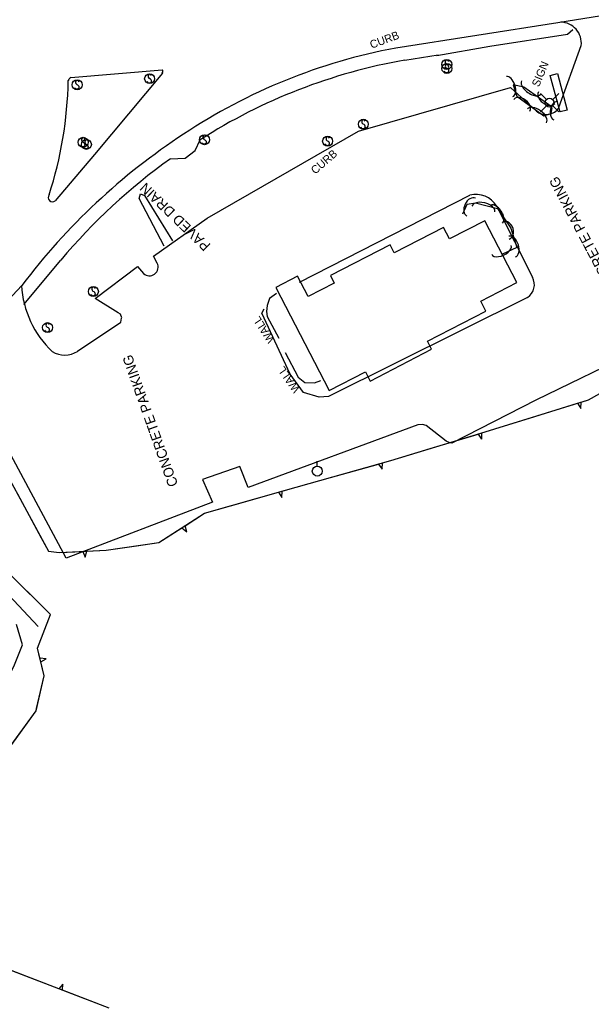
# Model space of a CAD drawing. Extents: x 978516 to 993312, y 1836504 to 1846212.
# Drawn here: x 980525.8 to 980811.4, y 1841850.4 to 1842344.4 of the extents above; entities that cross this region are included whole.
import ezdxf

# ---------------------------------------------------------------- set-up
doc = ezdxf.new("R2010")
doc.units = 0
for name, color, linetype in [('S_BUILDING', 7, 'Continuous'), ('S_CURB_ANNOT', 7, 'Continuous'), ('S_DROP_INLET', 7, 'Continuous'), ('S_EDGE_PAVEMENT', 7, 'Continuous'), ('S_PARKING', 7, 'Continuous'), ('S_PARKING_ANNOT', 7, 'Continuous'), ('S_SIDE_DRAIN', 7, 'Continuous'), ('S_SIDE_DRAIN_ANNOT', 7, 'Continuous'), ('S_SIDEWALK', 7, 'Continuous'), ('S_SIGN', 7, 'Continuous'), ('S_SIGN_ANNOT', 7, 'Continuous'), ('S_TREE', 7, 'Continuous'), ('S_UTILITY_POLE', 7, 'Continuous'), ('S_WALL', 7, 'Continuous'), ('S_WALL_ANNOT', 7, 'Continuous')]:
    doc.layers.add(name, color=color, linetype=linetype)

msp = doc.modelspace()

# ---------------------------------------------------------------- linework, layer by layer
at = {"layer": 'S_BUILDING'}
msp.add_lwpolyline([(980700.89, 1842163.85), (980731.67, 1842179.7), (980729.61, 1842183.71), (980758.77, 1842198.73), (980756.17, 1842203.79), (980774.22, 1842213.08), (980758.31, 1842243.96), (980740.63, 1842234.85), (980737.66, 1842240.61), (980712.96, 1842227.89), (980710.86, 1842231.94), (980681.03, 1842216.57), (980682.95, 1842212.83), (980669.89, 1842206.1), (980664.67, 1842216.24), (980653.78, 1842210.63), (980680.36, 1842159.05), (980698.54, 1842168.41)], close=True, dxfattribs=at)
at = {"layer": 'S_DROP_INLET'}
msp.add_lwpolyline([(980461.72, 1842118.58), (980485.79, 1842093.54), (980535.01, 1842041.17)], dxfattribs=at)
at = {"layer": 'S_EDGE_PAVEMENT'}
for points in [[(980872.65, 1842355.57), (980794.78, 1842342.82), (980713.74, 1842330.18)], [(980597.11, 1842317.76), (980563.11, 1842277.02), (980543.49, 1842253.94)], [(980551.27, 1842315.59), (980596.92, 1842319.34)], [(980526.84, 1842211.65), (980496.07, 1842178.69), (980502.46, 1842172.05), (980485.06, 1842161.67), (980426.92, 1842109.86), (980373.5, 1842064.99), (980287.46, 1842001.41), (980221.84, 1841941.16)]]:
    msp.add_lwpolyline(points, dxfattribs=at)
for centre, major_axis, ratio, start_param, end_param in [((980765.1, 1842049.98), (-229.09, -170.43), 0.997139, 4.255192, 4.658729), ((980596.2, 1842318.54), (-1.11, 0.35), 0.900674, 2.662056, 4.321878), ((980352.91, 1842317.49), (-4.34, 197.11), 0.999815, 4.377701, 4.672966), ((980551.39, 1842314), (-1.43, -1.93), 0.506002, 4.184868, 5.040843), ((980784.71, 1842016.69), (-195.91, -257.44), 0.999274, 4.37175, 4.715519), ((980542.05, 1842255.46), (1.56, -1.4), 0.94498, 3.153441, 6.199919)]:
    msp.add_ellipse(centre, major_axis=major_axis, ratio=ratio, start_param=start_param, end_param=end_param, dxfattribs=at)
at = {"layer": 'S_PARKING'}
for points in [[(980795.29, 1842300.49), (980806.46, 1842331.5)], [(980594.47, 1842222.78), (980592.69, 1842226.28), (980619.4, 1842245.28), (980695.16, 1842288.74), (980771.13, 1842310.53), (980784.01, 1842298.77)], [(980665.66, 1842213.18), (980750.82, 1842256.69)], [(980764.16, 1842251.36), (980782.01, 1842215.73)], [(980576.85, 1842195.36), (980576.15, 1842197.34), (980574.96, 1842197.91), (980563.49, 1842205.17), (980584.67, 1842221.04), (980587.66, 1842217.55)], [(980779.57, 1842205.59), (980680.15, 1842156.16), (980675.38, 1842155.77), (980667.53, 1842158.18), (980660.92, 1842167.3), (980646.85, 1842197.73), (980647.93, 1842199.99)], [(980576.22, 1842193.31), (980576.63, 1842195.32)], [(980554.69, 1842178.69), (980576.22, 1842193.31)], [(980828.79, 1842184.69), (980834.04, 1842181.4), (980834.52, 1842178.98), (980783.67, 1842154.28), (980741.81, 1842132.74), (980740.35, 1842133.1), (980738.88, 1842133.8), (980728.87, 1842141.55), (980727.15, 1842142.2), (980724.76, 1842141.92), (980639.94, 1842110.6), (980635.81, 1842121.12), (980617.08, 1842114.71), (980622.17, 1842103.33), (980548.9, 1842075.38), (980511.23, 1842145.54)], [(980278.9, 1841923.42), (980289.26, 1841945.13), (980294.63, 1841955.98), (980303.11, 1841959.51), (980312.56, 1841962.69), (980375.12, 1841958.32), (980401.56, 1841955.07), (980432.75, 1841952.79), (980461.29, 1841946.67), (980488.37, 1841958.3), (980503.82, 1841981.51), (980510.91, 1841996.34), (980516.9, 1842008.88), (980523.17, 1842022.04), (980527.22, 1842031.99), (980524.16, 1842042.13)]]:
    msp.add_lwpolyline(points, dxfattribs=at)
for centre, major_axis, ratio, start_param, end_param in [((980796.25, 1842332.81), (-5.18, 9.07), 0.977926, 4.075706, 5.754692), ((980789.27, 1842302.63), (-6.67, -1.36), 0.81419, 0.515551, 2.504505), ((980753.74, 1842244.62), (-9.29, 8.25), 0.998387, 4.442087, 5.675257), ((980590.66, 1842220.71), (-2.76, -3.37), 0.964306, 6.208064, 9.025071), ((980775.48, 1842211.91), (4.8, 5.85), 0.993135, 4.405291, 5.926664), ((980573.77, 1842213.98), (9.89, -47.23), 0.976969, 4.560043, 5.333899), ((980548.41, 1842188.34), (-11.18, -3.48), 0.982478, 0.695318, 1.841397)]:
    msp.add_ellipse(centre, major_axis=major_axis, ratio=ratio, start_param=start_param, end_param=end_param, dxfattribs=at)
at = {"layer": 'S_SIDE_DRAIN'}
msp.add_lwpolyline([(980597.99, 1842231.3), (980585.48, 1842255.11), (980586.16, 1842257.45), (980588.16, 1842256.5), (980602.05, 1842233.83)], dxfattribs=at)
at = {"layer": 'S_SIDEWALK'}
for points in [[(980802.18, 1842339.35), (980799.62, 1842336.97), (980760.69, 1842331), (980734.18, 1842326.43)], [(980718.21, 1842324.15), (980734.95, 1842326.87)], [(980601.1, 1842274.96), (980608.43, 1842275.14), (980613.44, 1842279.04), (980616.02, 1842284.45)], [(980527.82, 1842202.09), (980546.31, 1842224.29)]]:
    msp.add_lwpolyline(points, dxfattribs=at)
for centre, major_axis, ratio, start_param, end_param in [((980764.62, 1842052.45), (-248.21, -123.64), 0.993462, 4.421252, 4.819223), ((980774.04, 1842033.66), (-249.41, -163.64), 0.995214, 4.753385, 5.004273)]:
    msp.add_ellipse(centre, major_axis=major_axis, ratio=ratio, start_param=start_param, end_param=end_param, dxfattribs=at)
at = {"layer": 'S_SIGN'}
msp.add_lwpolyline([(980795.86, 1842298.27), (980790.86, 1842316.5), (980794.6, 1842317.59), (980799.4, 1842299.12), (980795.86, 1842298.38)], dxfattribs=at)
for centre in [(980739.23, 1842322.05), (980739.3, 1842320.05), (980590.69, 1842314.94), (980554.48, 1842311.89), (980697.52, 1842292.16), (980557.44, 1842283.14), (980559.07, 1842282.09), (980618.13, 1842284.43), (980679.68, 1842283.7), (980562.57, 1842208.58), (980539.68, 1842190.55)]:
    msp.add_circle(centre, 2.49, dxfattribs=at)
for centre, radius, start, end in [((980739.92, 1842323.37), 1.5, 167.1196, 241.9813), ((980739.31, 1842323.31), 0.95, 16.5258, 156.8957), ((980739.37, 1842321.32), 0.95, 16.5258, 156.8957), ((980739.08, 1842321.22), 1.28, 204.641, 335.359), ((980739.14, 1842319.23), 1.28, 204.641, 335.359), ((980739.98, 1842321.37), 1.5, 167.1196, 241.9813), ((980738.82, 1842320.7), 1.4, 358.6529, 73.7063), ((980738.88, 1842318.71), 1.4, 358.6529, 73.7063), ((980555.16, 1842313.21), 1.5, 167.1196, 241.9813), ((980554.55, 1842313.16), 0.95, 16.5258, 156.8957), ((980590.54, 1842314.12), 1.28, 204.641, 335.359), ((980591.38, 1842316.27), 1.5, 167.1196, 241.9813), ((980590.77, 1842316.21), 0.95, 16.5258, 156.8957), ((980590.28, 1842313.6), 1.4, 358.6529, 73.7063), ((980554.32, 1842311.06), 1.28, 204.641, 335.359), ((980554.07, 1842310.55), 1.4, 358.6529, 73.7063), ((980698.21, 1842293.49), 1.5, 167.1196, 241.9813), ((980697.59, 1842293.43), 0.95, 16.5258, 156.8957), ((980697.37, 1842291.34), 1.28, 204.641, 335.359), ((980697.11, 1842290.82), 1.4, 358.6529, 73.7063), ((980558.13, 1842284.46), 1.5, 167.1196, 241.9813), ((980557.51, 1842284.41), 0.95, 16.5258, 156.8957), ((980557.03, 1842281.8), 1.4, 358.6529, 73.7063), ((980559.76, 1842283.42), 1.5, 167.1196, 241.9813), ((980559.15, 1842283.36), 0.95, 16.5258, 156.8957), ((980617.97, 1842283.61), 1.28, 204.641, 335.359), ((980618.81, 1842285.75), 1.5, 167.1196, 241.9813), ((980618.2, 1842285.7), 0.95, 16.5258, 156.8957), ((980617.71, 1842283.09), 1.4, 358.6529, 73.7063), ((980680.36, 1842285.03), 1.5, 167.1196, 241.9813), ((980679.75, 1842284.97), 0.95, 16.5258, 156.8957), ((980679.26, 1842282.36), 1.4, 358.6529, 73.7063), ((980557.29, 1842282.32), 1.28, 204.641, 335.359), ((980558.92, 1842281.27), 1.28, 204.641, 335.359), ((980558.66, 1842280.75), 1.4, 358.6529, 73.7063), ((980679.52, 1842282.88), 1.28, 204.641, 335.359), ((980563.26, 1842209.91), 1.5, 167.1196, 241.9813), ((980562.65, 1842209.85), 0.95, 16.5258, 156.8957), ((980562.16, 1842207.24), 1.4, 358.6529, 73.7063), ((980562.42, 1842207.76), 1.28, 204.641, 335.359), ((980539.53, 1842189.73), 1.28, 204.641, 335.359), ((980540.37, 1842191.88), 1.5, 167.1196, 241.9813), ((980539.76, 1842191.82), 0.95, 16.5258, 156.8957), ((980539.27, 1842189.21), 1.4, 358.6529, 73.7063)]:
    msp.add_arc(centre, radius, start, end, dxfattribs=at)
at = {"layer": 'S_TREE'}
for p, q in [((980804.5, 1842152.76), (980806.29, 1842150.17)), ((980806.29, 1842150.17), (980806.38, 1842153.34)), ((980754.89, 1842137.37), (980756.66, 1842134.78)), ((980756.68, 1842134.78), (980756.77, 1842137.95)), ((980705.13, 1842122.37), (980706.85, 1842119.74)), ((980706.85, 1842119.74), (980707.03, 1842122.91)), ((980655.11, 1842108.32), (980656.84, 1842105.7)), ((980656.84, 1842105.7), (980657, 1842108.86)), ((980606.82, 1842090.49), (980609.22, 1842088.47)), ((980609.22, 1842088.47), (980608.46, 1842091.55)), ((980557.37, 1842078.72), (980558.48, 1842075.78)), ((980558.48, 1842075.78), (980559.33, 1842078.83)), ((980539.01, 1842025.1), (980535.86, 1842025.4)), ((980536.3, 1842023.55), (980539.01, 1842025.1)), ((980547.36, 1841862.53), (980545.33, 1841860.1)), ((980547.16, 1841859.39), (980547.36, 1841862.53))]:
    msp.add_line(p, q, dxfattribs=at)
for points in [[(980791.96, 1842300.75), (980777.74, 1842310.7), (980772.49, 1842311.84), (980774.3, 1842306.22), (980787.69, 1842296.4), (980791.36, 1842297.56), (980791.98, 1842300.39)], [(980747.18, 1842247.33), (980749.5, 1842252.21), (980753.52, 1842252.94), (980764.57, 1842250.13), (980771.23, 1842240.27), (980774.28, 1842230.55), (980767.06, 1842227.31)], [(980518.51, 1842118.77), (980540.15, 1842078.82), (980545.53, 1842078.08), (980569.03, 1842079.35), (980595.37, 1842083.12), (980618.2, 1842097.82), (980658.69, 1842109.34), (980711.34, 1842124.12), (980756.27, 1842137.79), (980810.15, 1842154.51), (980852.32, 1842178.17)], [(980806.38, 1842153.34), (980810.15, 1842154.51), (980828.5, 1842164.81)], [(980780.63, 1842145.35), (980804.5, 1842152.76)], [(980756.77, 1842137.95), (980780.63, 1842145.35)], [(980730.97, 1842130.09), (980754.89, 1842137.37)], [(980707.03, 1842122.91), (980711.34, 1842124.12), (980730.97, 1842130.09)], [(980681.06, 1842115.62), (980705.13, 1842122.37)], [(980657, 1842108.86), (980658.69, 1842109.34), (980681.06, 1842115.62)], [(980524.6, 1842107.53), (980536.51, 1842085.55)], [(980631.06, 1842101.48), (980655.11, 1842108.32)], [(980608.46, 1842091.55), (980618.2, 1842097.82), (980631.06, 1842101.48)], [(980584.15, 1842081.52), (980595.37, 1842083.12), (980606.82, 1842090.49)], [(980536.51, 1842085.55), (980540.15, 1842078.82), (980545.53, 1842078.08), (980557.37, 1842078.72)], [(980559.33, 1842078.83), (980569.03, 1842079.35), (980584.15, 1842081.52)], [(980505.43, 1841959.92), (980533.97, 1841999.04), (980537.95, 1842016.48), (980534.71, 1842030.34), (980541.08, 1842047.26), (980517.44, 1842070.63)], [(980540.01, 1842048.31), (980522.42, 1842065.71)], [(980535.86, 1842025.4), (980534.71, 1842030.34), (980541.08, 1842047.26), (980540.01, 1842048.31)], [(980534.22, 1842000.14), (980537.95, 1842016.48), (980536.3, 1842023.55)], [(980520.17, 1841980.13), (980533.97, 1841999.04), (980534.22, 1842000.14)], [(980570.5, 1841850.43), (980499.15, 1841877.84)], [(980545.33, 1841860.1), (980522, 1841869.07)], [(980570.5, 1841850.43), (980547.16, 1841859.39)]]:
    msp.add_lwpolyline(points, dxfattribs=at)
for centre, major_axis, ratio, start_param, end_param in [((980770.61, 1842310.97), (-1.7, 4.97), 0.532719, 3.106703, 6.248295), ((980781.45, 1842310.55), (4.79, -3.38), 0.521229, 3.14915, 6.290743), ((980789.17, 1842305.45), (4.04, -2.87), 0.649342, 3.153449, 6.295042), ((980776.69, 1842301.67), (-4.02, 2.9), 0.649561, 3.128646, 6.270239), ((980793.82, 1842298.94), (-0.84, -4.56), 0.618944, 3.085351, 6.226944), ((980784.3, 1842296.39), (-4.74, 3.45), 0.521409, 3.133343, 6.274935), ((980751.45, 1842250.78), (-2.13, -4.47), 0.682344, 3.141593, 6.283185), ((980757.52, 1842249.78), (-5.69, 1.44), 0.537794, 3.139974, 6.281567), ((980764.01, 1842247.2), (-3, 4.43), 0.536519, 3.140441, 6.282034), ((980769.09, 1842239.15), (-1.51, 4.33), 0.738154, 3.099644, 6.241237), ((980771.91, 1842231.05), (-1.7, 5.16), 0.592755, 3.117976, 6.259568), ((980766.54, 1842229.35), (4.83, 2.22), 0.532609, 3.125603, 6.267196)]:
    msp.add_ellipse(centre, major_axis=major_axis, ratio=ratio, start_param=start_param, end_param=end_param, dxfattribs=at)
at = {"layer": 'S_UTILITY_POLE'}
for p, q in [((980789, 1842304.55), (980786.01, 1842307.54)), ((980792.17, 1842304.55), (980795.16, 1842307.54)), ((980789, 1842301.38), (980786.01, 1842298.39)), ((980792.17, 1842301.38), (980795.16, 1842298.39)), ((980674.37, 1842121.38), (980674.37, 1842123.86))]:
    msp.add_line(p, q, dxfattribs=at)
for centre, radius in [((980790.59, 1842302.97), 2.21), ((980674.51, 1842118.86), 2.5)]:
    msp.add_circle(centre, radius, dxfattribs=at)
at = {"layer": 'S_WALL'}
for points in [[(980654.12, 1842207.67), (980650.66, 1842205.13), (980649.47, 1842201.52), (980649.05, 1842198.54), (980649.38, 1842196.12), (980655.27, 1842185.22)], [(980658.48, 1842178.17), (980664.89, 1842165.86), (980668.29, 1842163.15), (980673.13, 1842162.93), (980676.22, 1842164.14)]]:
    msp.add_lwpolyline(points, dxfattribs=at)

# ---------------------------------------------------------------- texts
at = {"layer": 'S_CURB_ANNOT'}
for rotation, p in [(20.2761, (980701.66, 1842329.86)), (41.0141, (980673.46, 1842266.93))]:
    msp.add_text('CURB', height=4, rotation=rotation, dxfattribs=at).set_placement(p)
at = {"layer": 'S_PARKING_ANNOT'}
for rotation, p in [(117.8406, (980827, 1842205.19)), (109.6153, (980605, 1842112.06))]:
    msp.add_text('CONCRETE PARKING', height=5.0005, rotation=rotation, dxfattribs=at).set_placement(p)
at = {"layer": 'S_SIDE_DRAIN_ANNOT'}
msp.add_text('PAVED DRAIN', height=5.0005, rotation=136.1241, dxfattribs=at).set_placement((980621.47, 1842231.94))
at = {"layer": 'S_SIGN_ANNOT'}
msp.add_text('SIGN', height=4, rotation=67.4076, dxfattribs=at).set_placement((980785.27, 1842310.49))
at = {"layer": 'S_WALL_ANNOT'}
for rotation, p in [(123.121, (980653.39, 1842184.49)), (124.9318, (980666.09, 1842159.76))]:
    msp.add_text('WALL', height=4, rotation=rotation, dxfattribs=at).set_placement(p)

doc.saveas('drawing.dxf')
